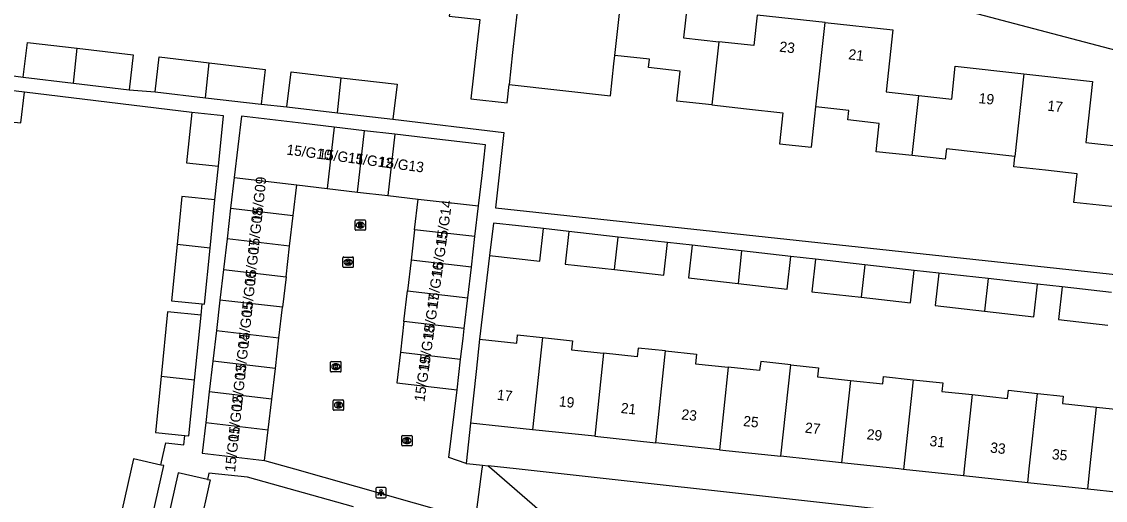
# Model space of a CAD drawing. Extents: x 162026 to 163499, y 387297 to 388169.
# Drawn here: x 162314.8 to 162419.5, y 387747 to 387793.2 of the extents above; entities that cross this region are included whole.
import ezdxf

# ---------------------------------------------------------------- set-up
doc = ezdxf.new("R2010")
doc.units = 0
for name, color, linetype in [('IMGEO_Kolk', 7, 'Continuous'), ('IMGEO_Lichtpunt', 7, 'Continuous'), ('IMGEO_Pand', 7, 'Continuous'), ('IMGEO_Pand_nummerreeks', 7, 'Continuous'), ('IMGEO_Rijbaan_lokaal_open', 7, 'Continuous'), ('IMGEO_Rioolput', 7, 'Continuous'), ('IMGEO_Voetpad_open', 7, 'Continuous')]:
    doc.layers.add(name, color=color, linetype=linetype)

msp = doc.modelspace()

# ---------------------------------------------------------------- linework, layer by layer
at = {"layer": 'IMGEO_Kolk'}
for p, q in [((162345.82, 387769.55), (162345.82, 387770.4)), ((162345.9, 387770.47), (162346.75, 387770.47)), ((162346.31, 387770.25), (162346.33, 387770.25)), ((162346.33, 387769.69), (162346.31, 387769.69)), ((162346.82, 387770.4), (162346.82, 387769.55)), ((162346.75, 387769.47), (162345.9, 387769.47)), ((162344.63, 387759.45), (162344.63, 387760.3)), ((162344.71, 387760.38), (162345.56, 387760.38)), ((162345.63, 387760.3), (162345.63, 387759.45)), ((162345.56, 387759.38), (162344.71, 387759.38)), ((162345.12, 387760.16), (162345.15, 387760.16)), ((162345.14, 387759.6), (162345.12, 387759.6)), ((162351.51, 387752.31), (162351.51, 387753.16)), ((162351.58, 387753.24), (162352.43, 387753.24)), ((162351.99, 387753.01), (162352.02, 387753.01)), ((162352.51, 387753.16), (162352.51, 387752.31)), ((162352.43, 387752.23), (162351.58, 387752.23)), ((162352.02, 387752.46), (162351.99, 387752.46))]:
    msp.add_line(p, q, dxfattribs=at)
for points in [[(162345.82, 387769.55), (162345.82, 387770.4)], [(162345.9, 387770.47), (162346.75, 387770.47)], [(162346.14, 387770.17), (162346.27, 387770.17), (162346.27, 387770.02), (162346.39, 387770.17), (162346.56, 387770.17), (162346.41, 387770.02), (162346.57, 387769.77), (162346.41, 387769.77), (162346.33, 387769.94), (162346.27, 387769.87), (162346.27, 387769.77), (162346.14, 387769.77), (162346.14, 387770.17)], [(162346.82, 387770.4), (162346.82, 387769.55)], [(162346.75, 387769.47), (162345.9, 387769.47)], [(162344.63, 387759.45), (162344.63, 387760.3)], [(162344.71, 387760.38), (162345.56, 387760.38)], [(162345.63, 387760.3), (162345.63, 387759.45)], [(162345.56, 387759.38), (162344.71, 387759.38)], [(162344.95, 387760.08), (162345.08, 387760.08), (162345.08, 387759.92), (162345.21, 387760.08), (162345.37, 387760.08), (162345.23, 387759.93), (162345.38, 387759.68), (162345.23, 387759.68), (162345.14, 387759.84), (162345.08, 387759.77), (162345.08, 387759.68), (162344.95, 387759.68), (162344.95, 387760.08)], [(162351.51, 387752.31), (162351.51, 387753.16)], [(162351.58, 387753.24), (162352.43, 387753.24)], [(162351.83, 387752.93), (162351.95, 387752.93), (162351.95, 387752.78), (162352.08, 387752.93), (162352.24, 387752.93), (162352.1, 387752.78), (162352.25, 387752.53), (162352.1, 387752.53), (162352.01, 387752.7), (162351.95, 387752.63), (162351.95, 387752.53), (162351.83, 387752.53), (162351.83, 387752.93)], [(162352.51, 387753.16), (162352.51, 387752.31)], [(162352.43, 387752.23), (162351.58, 387752.23)]]:
    msp.add_lwpolyline(points, dxfattribs=at)
for centre, start, end in [((162345.9, 387770.4), 91.552, 178.448), ((162345.9, 387770.4), 91.552, 178.448), ((162346.75, 387770.4), 1.552, 88.448), ((162346.75, 387770.4), 1.552, 88.448), ((162345.9, 387769.55), 181.552, 268.448), ((162345.9, 387769.55), 181.552, 268.448), ((162346.75, 387769.55), 271.552, 358.448), ((162346.75, 387769.55), 271.552, 358.448), ((162344.71, 387760.3), 91.552, 178.448), ((162344.71, 387760.3), 91.552, 178.448), ((162345.56, 387760.3), 1.552, 88.448), ((162345.56, 387760.3), 1.552, 88.448), ((162344.71, 387759.45), 181.552, 268.448), ((162344.71, 387759.45), 181.552, 268.448), ((162345.56, 387759.45), 271.552, 358.448), ((162345.56, 387759.45), 271.552, 358.448), ((162351.58, 387753.16), 91.552, 178.448), ((162351.58, 387753.16), 91.552, 178.448), ((162352.43, 387753.16), 1.552, 88.448), ((162352.43, 387753.16), 1.552, 88.448), ((162351.58, 387752.31), 181.552, 268.448), ((162351.58, 387752.31), 181.552, 268.448), ((162352.43, 387752.31), 271.552, 358.448), ((162352.43, 387752.31), 271.552, 358.448)]:
    msp.add_arc(centre, 0.0765, start, end, dxfattribs=at)
for centre, major_axis, ratio, start_param, end_param in [((162346.31, 387769.97), (-0.387, 0.002), 0.722429, 4.712389, 7.853982), ((162346.33, 387769.97), (-0.39, 0.002), 0.717154, 1.570796, 4.712389), ((162345.12, 387759.88), (-0.387, 0.002), 0.722429, 4.712389, 7.853982), ((162345.14, 387759.88), (-0.39, 0.002), 0.717154, 1.570796, 4.712389), ((162351.99, 387752.73), (-0.387, 0.002), 0.722429, 4.712389, 7.853982), ((162352.02, 387752.73), (-0.39, 0.002), 0.717154, 1.570796, 4.712389)]:
    msp.add_ellipse(centre, major_axis=major_axis, ratio=ratio, start_param=start_param, end_param=end_param, dxfattribs=at)
at = {"layer": 'IMGEO_Lichtpunt'}
for p, q in [((162349, 387748.11), (162349, 387747.3)), ((162349, 387748.11), (162349, 387747.3)), ((162349.91, 387748.2), (162349.1, 387748.2)), ((162349.91, 387748.2), (162349.1, 387748.2)), ((162350, 387747.3), (162350, 387748.11)), ((162350, 387747.3), (162350, 387748.11)), ((162349.1, 387747.2), (162349.91, 387747.2)), ((162349.1, 387747.2), (162349.91, 387747.2))]:
    msp.add_line(p, q, dxfattribs=at)
for points in [[(162349.38, 387747.77), (162349.42, 387747.74), (162349.23, 387747.48), (162349.19, 387747.51), (162349.38, 387747.77)], [(162349.48, 387747.72), (162349.53, 387747.72), (162349.53, 387747.4), (162349.48, 387747.4), (162349.48, 387747.72)], [(162349.59, 387747.74), (162349.63, 387747.77), (162349.81, 387747.51), (162349.78, 387747.48), (162349.59, 387747.74)]]:
    msp.add_lwpolyline(points, dxfattribs=at)
msp.add_circle((162349.5, 387747.9), 0.0994, dxfattribs=at)
for centre, start, end in [((162349.1, 387748.11), 90, 180), ((162349.1, 387748.11), 90, 180), ((162349.91, 387748.11), 0, 90), ((162349.91, 387748.11), 0, 90), ((162349.1, 387747.3), 180, 270), ((162349.1, 387747.3), 180, 270), ((162349.91, 387747.3), 270, 0), ((162349.91, 387747.3), 270, 360)]:
    msp.add_arc(centre, 0.0946, start, end, dxfattribs=at)
at = {"layer": 'IMGEO_Pand'}
for points in [[(162372.11, 387789.95), (162373.03, 387798.34)], [(162373.03, 387798.34), (162379.42, 387797.64), (162378.76, 387791.64), (162382.16, 387791.26)], [(162362.89, 387796.24), (162362.22, 387790.21), (162361.89, 387787.14)], [(162352.89, 387795.33), (162356.24, 387794.96), (162356.1, 387793.73), (162359.05, 387793.4), (162358.72, 387790.6), (162358.19, 387785.76), (162361.69, 387785.37), (162361.89, 387787.14)], [(162392.44, 387793.12), (162385.88, 387793.84), (162385.56, 387790.89), (162382.16, 387791.26)], [(162391.54, 387784.98), (162392.44, 387793.12)], [(162392.44, 387793.12), (162399, 387792.4), (162398.35, 387786.42), (162401.51, 387786.07)], [(162314.91, 387787.83), (162315.31, 387791.2), (162320.14, 387790.63)], [(162319.77, 387787.26), (162320.14, 387790.63)], [(162320.14, 387790.63), (162325.55, 387789.99), (162325.15, 387786.62)], [(162382.16, 387791.26), (162381.49, 387785.16)], [(162327.66, 387786.43), (162328.06, 387789.8), (162332.9, 387789.23)], [(162361.89, 387787.14), (162371.68, 387786.05), (162372.02, 387789.13), (162372.11, 387789.95)], [(162381.49, 387785.16), (162378.1, 387785.53), (162378.41, 387788.43), (162375.37, 387788.77), (162375.46, 387789.58), (162372.11, 387789.95)], [(162332.53, 387785.85), (162332.9, 387789.23)], [(162332.9, 387789.23), (162338.31, 387788.59), (162337.91, 387785.22)], [(162401.51, 387786.07), (162404.68, 387785.72), (162405.02, 387788.89), (162411.66, 387788.16)], [(162314.91, 387787.83), (162319.77, 387787.26)], [(162340.41, 387784.99), (162340.81, 387788.36), (162345.65, 387787.79)], [(162345.28, 387784.41), (162345.65, 387787.79)], [(162345.65, 387787.79), (162351.05, 387787.15), (162350.66, 387783.78)], [(162411.66, 387788.16), (162410.78, 387780.19)], [(162411.66, 387788.16), (162418.29, 387787.43), (162417.64, 387781.53), (162420.88, 387781.17)], [(162315.03, 387786.39), (162310.9, 387786.86), (162305.93, 387787.42)], [(162313.29, 387780.17), (162313.67, 387783.54), (162314.69, 387783.42), (162315.03, 387786.39)], [(162319.77, 387787.26), (162325.15, 387786.62)], [(162327.66, 387786.43), (162332.53, 387785.85)], [(162332.53, 387785.85), (162337.91, 387785.22)], [(162400.87, 387780.26), (162401.51, 387786.07)], [(162331.21, 387784.43), (162330.7, 387779.57), (162333.78, 387779.25)], [(162333.78, 387779.25), (162334.28, 387784.11), (162331.21, 387784.43)], [(162340.41, 387784.99), (162345.28, 387784.41)], [(162345.28, 387784.41), (162350.66, 387783.78)], [(162381.49, 387785.16), (162384.83, 387784.79), (162388.36, 387784.4), (162388.03, 387781.41), (162391.11, 387781.07), (162391.44, 387784.06), (162391.54, 387784.98)], [(162400.87, 387780.26), (162397.39, 387780.64), (162397.68, 387783.38), (162394.64, 387783.71), (162394.74, 387784.63), (162391.54, 387784.98)], [(162344.98, 387783.02), (162342.04, 387783.36), (162336, 387784.06), (162335.65, 387781.1), (162335.31, 387778.15)], [(162344.98, 387783.02), (162344.29, 387777.09)], [(162347.91, 387782.67), (162344.98, 387783.02)], [(162347.22, 387776.74), (162347.91, 387782.67)], [(162350.85, 387782.33), (162347.91, 387782.67)], [(162350.85, 387782.33), (162350.16, 387776.4)], [(162358.93, 387775.4), (162359.27, 387778.35), (162359.62, 387781.31), (162353.79, 387781.99), (162350.85, 387782.33)], [(162410.78, 387780.19), (162404.17, 387780.92), (162404.06, 387779.91), (162400.87, 387780.26)], [(162420.17, 387775.34), (162416.5, 387775.75), (162416.81, 387778.51), (162413.74, 387778.85), (162410.67, 387779.18), (162410.78, 387780.19)], [(162335.31, 387778.15), (162334.96, 387775.19)], [(162335.31, 387778.15), (162341.35, 387777.43)], [(162341.01, 387774.48), (162341.35, 387777.43)], [(162341.35, 387777.43), (162344.29, 387777.09)], [(162344.29, 387777.09), (162347.22, 387776.74)], [(162333.44, 387775.98), (162330.25, 387776.3), (162329.79, 387771.69)], [(162332.98, 387771.32), (162333.44, 387775.98)], [(162347.22, 387776.74), (162350.16, 387776.4)], [(162350.16, 387776.4), (162353.1, 387776.06)], [(162352.75, 387773.11), (162353.1, 387776.06)], [(162353.1, 387776.06), (162358.93, 387775.4)], [(162334.96, 387775.19), (162334.62, 387772.23)], [(162334.96, 387775.19), (162341.01, 387774.48)], [(162358.58, 387772.44), (162358.93, 387775.4)], [(162340.66, 387771.53), (162341.01, 387774.48)], [(162352.75, 387773.11), (162352.41, 387770.16)], [(162358.58, 387772.44), (162352.75, 387773.11)], [(162365.2, 387773.21), (162360.39, 387773.75), (162360, 387770.61)], [(162360, 387770.61), (162364.85, 387770.07), (162365.2, 387773.21)], [(162367.66, 387772.93), (162367.31, 387769.79), (162372.08, 387769.26)], [(162372.43, 387772.4), (162367.66, 387772.93)], [(162334.62, 387772.23), (162334.27, 387769.27)], [(162340.66, 387771.53), (162334.62, 387772.23)], [(162358.24, 387769.48), (162358.58, 387772.44)], [(162372.08, 387769.26), (162372.43, 387772.4)], [(162372.08, 387769.26), (162376.86, 387768.72), (162377.21, 387771.86)], [(162377.21, 387771.86), (162372.43, 387772.4)], [(162329.79, 387771.69), (162329.24, 387766.25), (162332.21, 387765.95)], [(162332.98, 387771.32), (162329.79, 387771.69)], [(162332.21, 387765.95), (162332.44, 387765.93), (162332.98, 387771.32)], [(162340.32, 387768.57), (162340.66, 387771.53)], [(162379.59, 387771.6), (162379.24, 387768.45), (162384.02, 387767.92)], [(162384.35, 387771.06), (162379.59, 387771.6)], [(162384.35, 387771.06), (162384.02, 387767.92)], [(162389.12, 387770.53), (162384.35, 387771.06)], [(162352.41, 387770.16), (162352.06, 387767.2)], [(162358.24, 387769.48), (162352.41, 387770.16)], [(162384.02, 387767.92), (162388.76, 387767.38), (162389.12, 387770.53)], [(162391.5, 387770.26), (162391.14, 387767.12), (162395.91, 387766.58)], [(162396.27, 387769.72), (162391.5, 387770.26)], [(162396.27, 387769.72), (162395.91, 387766.58)], [(162401.05, 387769.18), (162396.27, 387769.72)], [(162334.27, 387769.27), (162333.93, 387766.31)], [(162334.27, 387769.27), (162340.32, 387768.57)], [(162357.89, 387766.52), (162358.24, 387769.48)], [(162395.91, 387766.58), (162400.7, 387766.04), (162401.05, 387769.18)], [(162403.43, 387768.92), (162403.08, 387765.78), (162407.85, 387765.24)], [(162408.2, 387768.38), (162403.43, 387768.92)], [(162340.32, 387768.57), (162339.97, 387765.61)], [(162408.2, 387768.38), (162407.85, 387765.24)], [(162407.85, 387765.24), (162412.62, 387764.7), (162412.98, 387767.85)], [(162412.98, 387767.85), (162408.2, 387768.38)], [(162415.36, 387767.58), (162415.01, 387764.44), (162419.77, 387763.9)], [(162420.12, 387767.04), (162415.36, 387767.58)], [(162351.72, 387764.24), (162352.06, 387767.2)], [(162352.06, 387767.2), (162357.89, 387766.52)], [(162357.55, 387763.56), (162357.89, 387766.52)], [(162333.93, 387766.31), (162333.58, 387763.36)], [(162339.97, 387765.61), (162333.93, 387766.31)], [(162339.63, 387762.65), (162339.97, 387765.61)], [(162332.1, 387764.84), (162328.86, 387765.17), (162328.23, 387758.93)], [(162331.47, 387758.56), (162332.1, 387764.84)], [(162333.58, 387763.36), (162333.24, 387760.4)], [(162333.58, 387763.36), (162339.63, 387762.65)], [(162351.72, 387764.24), (162351.38, 387761.28)], [(162357.55, 387763.56), (162351.72, 387764.24)], [(162357.2, 387760.6), (162357.44, 387762.61), (162357.55, 387763.56)], [(162339.29, 387759.69), (162339.63, 387762.65)], [(162359.03, 387762.52), (162358.69, 387759.4), (162358.16, 387754.43)], [(162359.03, 387762.52), (162362.62, 387762.14), (162362.71, 387762.95), (162365.11, 387762.69)], [(162365.11, 387762.69), (162364.15, 387753.79)], [(162365.11, 387762.69), (162368.01, 387762.38), (162367.91, 387761.51), (162371.02, 387761.18)], [(162351.38, 387761.28), (162351.03, 387758.32), (162356.86, 387757.65)], [(162351.38, 387761.28), (162357.2, 387760.6)], [(162377.01, 387761.4), (162374.37, 387761.68), (162374.28, 387760.83), (162371.02, 387761.18)], [(162376.06, 387752.51), (162377.01, 387761.4)], [(162377.01, 387761.4), (162380, 387761.08), (162379.9, 387760.16), (162383.07, 387759.82)], [(162333.24, 387760.4), (162332.89, 387757.44)], [(162339.29, 387759.69), (162333.24, 387760.4)], [(162356.86, 387757.65), (162357.2, 387760.6)], [(162371.02, 387761.18), (162370.16, 387753.15)], [(162389.12, 387760.06), (162386.21, 387760.37), (162386.11, 387759.5), (162383.07, 387759.82)], [(162338.94, 387756.74), (162339.29, 387759.69)], [(162383.07, 387759.82), (162382.22, 387751.85)], [(162388.17, 387751.22), (162389.12, 387760.06)], [(162389.12, 387760.06), (162391.79, 387759.77), (162391.7, 387758.89), (162394.88, 387758.55)], [(162328.23, 387758.93), (162327.69, 387753.52), (162330.55, 387753.24)], [(162331.47, 387758.56), (162328.23, 387758.93)], [(162330.55, 387753.24), (162330.93, 387753.2), (162331.47, 387758.56)], [(162394.88, 387758.55), (162394.02, 387750.59)], [(162394.88, 387758.55), (162398.01, 387758.21), (162398.09, 387758.92), (162400.96, 387758.61)], [(162400.96, 387758.61), (162400.03, 387749.95)], [(162400.96, 387758.61), (162403.83, 387758.31), (162403.74, 387757.49), (162406.67, 387757.18)], [(162332.89, 387757.44), (162332.55, 387754.48)], [(162338.94, 387756.74), (162332.89, 387757.44)], [(162406.67, 387757.18), (162405.9, 387750), (162405.83, 387749.33)], [(162406.67, 387757.18), (162410.08, 387756.81), (162410.16, 387757.6), (162412.96, 387757.3)], [(162412.04, 387748.66), (162412.18, 387750), (162412.96, 387757.3)], [(162412.96, 387757.3), (162415.47, 387757.04), (162415.39, 387756.31), (162418.69, 387755.96)], [(162338.6, 387753.78), (162338.94, 387756.74)], [(162418.69, 387755.96), (162421.71, 387755.63), (162421.8, 387756.46), (162424.78, 387756.14)], [(162417.84, 387748.04), (162418.05, 387750), (162418.69, 387755.96)], [(162332.55, 387754.48), (162332.21, 387751.52), (162333.29, 387751.4), (162338.25, 387750.82)], [(162332.55, 387754.48), (162338.6, 387753.78)], [(162364.15, 387753.79), (162358.16, 387754.43)], [(162338.25, 387750.82), (162338.6, 387753.78)], [(162370.16, 387753.15), (162364.15, 387753.79)], [(162370.16, 387753.15), (162376.06, 387752.51)], [(162382.22, 387751.85), (162376.06, 387752.51)], [(162382.22, 387751.85), (162388.17, 387751.22)], [(162328.21, 387750.38), (162325.57, 387750.98), (162324.48, 387746.13)], [(162394.02, 387750.59), (162388.17, 387751.22)], [(162327.41, 387745.47), (162328.5, 387750.32), (162328.21, 387750.38)], [(162400.03, 387749.95), (162399.56, 387750), (162394.02, 387750.59)], [(162405.83, 387749.33), (162400.03, 387749.95)], [(162332.74, 387748.99), (162329.89, 387749.63), (162328.83, 387744.88)], [(162332.74, 387748.99), (162332.97, 387748.94), (162331.91, 387744.19), (162328.83, 387744.88)], [(162412.04, 387748.66), (162405.83, 387749.33)], [(162417.84, 387748.04), (162412.04, 387748.66)], [(162423.85, 387747.4), (162417.84, 387748.04)]]:
    msp.add_lwpolyline(points, dxfattribs=at)
at = {"layer": 'IMGEO_Rijbaan_lokaal_open'}
for points in [[(162357.75, 387750.54), (162356.07, 387751.11), (162356.86, 387757.65)], [(162338.25, 387750.82), (162341.15, 387750), (162358.62, 387745.05)], [(162357.75, 387750.54), (162357.8, 387750.52), (162359.31, 387750.36)], [(162359.31, 387750.36), (162359.26, 387750), (162358.62, 387745.05)]]:
    msp.add_lwpolyline(points, dxfattribs=at)
at = {"layer": 'IMGEO_Rioolput'}
for p, q in [((162347, 387773.13), (162347, 387773.98)), ((162347.08, 387774.05), (162347.93, 387774.05)), ((162347.49, 387773.83), (162347.52, 387773.83)), ((162348, 387773.98), (162348, 387773.13)), ((162347.93, 387773.05), (162347.08, 387773.05)), ((162347.51, 387773.27), (162347.49, 387773.27)), ((162344.89, 387755.74), (162344.89, 387756.59)), ((162344.96, 387756.67), (162345.82, 387756.67)), ((162345.38, 387756.45), (162345.4, 387756.45)), ((162345.89, 387756.59), (162345.89, 387755.74)), ((162345.82, 387755.67), (162344.96, 387755.67)), ((162345.4, 387755.89), (162345.37, 387755.89))]:
    msp.add_line(p, q, dxfattribs=at)
for points in [[(162347, 387773.13), (162347, 387773.98)], [(162347.08, 387774.05), (162347.93, 387774.05)], [(162348, 387773.98), (162348, 387773.13)], [(162347.93, 387773.05), (162347.08, 387773.05)], [(162347.59, 387773.75), (162347.34, 387773.75), (162347.34, 387773.35)], [(162347.34, 387773.35), (162347.46, 387773.35), (162347.46, 387773.51), (162347.47, 387773.51)], [(162347.52, 387773.67), (162347.46, 387773.67), (162347.46, 387773.59)], [(162347.46, 387773.59), (162347.51, 387773.59)], [(162347.52, 387773.48), (162347.59, 387773.35), (162347.73, 387773.35), (162347.67, 387773.48)], [(162344.89, 387755.74), (162344.89, 387756.59)], [(162344.96, 387756.67), (162345.82, 387756.67)], [(162345.48, 387756.37), (162345.22, 387756.37), (162345.22, 387755.97)], [(162345.22, 387755.97), (162345.35, 387755.97), (162345.35, 387756.13), (162345.36, 387756.13)], [(162345.4, 387756.29), (162345.35, 387756.29), (162345.35, 387756.21)], [(162345.35, 387756.21), (162345.4, 387756.21)], [(162345.41, 387756.1), (162345.48, 387755.97), (162345.62, 387755.97), (162345.55, 387756.09)], [(162345.89, 387756.59), (162345.89, 387755.74)], [(162345.82, 387755.67), (162344.96, 387755.67)]]:
    msp.add_lwpolyline(points, dxfattribs=at)
for centre, radius, start, end in [((162347.08, 387773.98), 0.0765, 91.552, 178.448), ((162347.08, 387773.98), 0.0765, 91.552, 178.448), ((162347.93, 387773.98), 0.0765, 1.552, 88.448), ((162347.93, 387773.98), 0.0765, 1.552, 88.448), ((162347.08, 387773.13), 0.0765, 181.552, 268.448), ((162347.08, 387773.13), 0.0765, 181.552, 268.448), ((162347.47, 387773.46), 0.0533, 26.0293, 88.6989), ((162347.5, 387773.78), 0.19, 274.7715, 282.9687), ((162347.52, 387773.57), 0.0964, 77.0061, 93.1865), ((162347.54, 387773.63), 0.0378, 276.6634, 79.6772), ((162347.59, 387773.64), 0.109, 350.3612, 89.416), ((162347.59, 387773.64), 0.112, 277.5842, 350.9817), ((162347.57, 387773.42), 0.108, 29.5134, 73.7905), ((162347.93, 387773.13), 0.0765, 271.552, 358.448), ((162347.93, 387773.13), 0.0765, 271.552, 358.448), ((162344.96, 387756.59), 0.0765, 91.552, 178.448), ((162344.96, 387756.59), 0.0765, 91.552, 178.448), ((162345.36, 387756.08), 0.0533, 26.0293, 88.6989), ((162345.41, 387756.19), 0.0964, 77.0061, 93.1865), ((162345.39, 387756.4), 0.19, 274.7715, 282.9687), ((162345.42, 387756.25), 0.0378, 276.6634, 79.6772), ((162345.48, 387756.26), 0.109, 350.3612, 89.416), ((162345.47, 387756.26), 0.112, 277.5842, 350.9817), ((162345.46, 387756.04), 0.108, 29.5134, 73.7905), ((162345.81, 387756.59), 0.0765, 1.552, 88.448), ((162345.81, 387756.59), 0.0765, 1.552, 88.448), ((162344.96, 387755.74), 0.0765, 181.552, 268.448), ((162344.96, 387755.74), 0.0765, 181.552, 268.448), ((162345.81, 387755.74), 0.0765, 271.552, 358.448), ((162345.81, 387755.74), 0.0765, 271.552, 358.448)]:
    msp.add_arc(centre, radius, start, end, dxfattribs=at)
for centre, major_axis, ratio, start_param, end_param in [((162347.49, 387773.55), (-0.387, 0.002), 0.722429, 4.712389, 7.853982), ((162347.51, 387773.55), (-0.39, 0.002), 0.717154, 1.570796, 4.712389), ((162345.38, 387756.17), (-0.387, 0.002), 0.722429, 4.712389, 7.853982), ((162345.4, 387756.17), (-0.39, 0.002), 0.717154, 1.570796, 4.712389)]:
    msp.add_ellipse(centre, major_axis=major_axis, ratio=ratio, start_param=start_param, end_param=end_param, dxfattribs=at)
at = {"layer": 'IMGEO_Voetpad_open'}
for points in [[(162302.74, 387811.36), (162304.73, 387812.66), (162306.96, 387812.39), (162360.93, 387806.15), (162438.18, 387785.81), (162484.71, 387780.32)], [(162313.5, 387788.05), (162314.91, 387787.83)], [(162331.21, 387784.43), (162315.03, 387786.39)], [(162325.15, 387786.62), (162327.66, 387786.43)], [(162337.91, 387785.22), (162340.41, 387784.99)], [(162350.66, 387783.78), (162361.38, 387782.51), (162360.57, 387775.22), (162425, 387768.3), (162427.31, 387767.66), (162435.36, 387763.78), (162433.89, 387752.27), (162448.74, 387751.33)], [(162333.44, 387775.98), (162333.78, 387779.25)], [(162367.66, 387772.93), (162365.2, 387773.21)], [(162379.59, 387771.6), (162377.21, 387771.86)], [(162360, 387770.61), (162359.03, 387762.52)], [(162391.5, 387770.26), (162389.12, 387770.53)], [(162403.43, 387768.92), (162401.05, 387769.18)], [(162415.36, 387767.58), (162412.98, 387767.85)], [(162332.1, 387764.84), (162332.21, 387765.95)], [(162358.16, 387754.43), (162357.75, 387750.54)], [(162328.21, 387750.38), (162328.28, 387750.68), (162328.7, 387752.52), (162330.44, 387752.32), (162330.55, 387753.24)], [(162359.31, 387750.36), (162359.87, 387750.3)], [(162431.24, 387742.32), (162427.03, 387742.86), (162362.56, 387750), (162359.87, 387750.3)], [(162359.87, 387750.3), (162360.21, 387750), (162366.56, 387744.51)], [(162346.84, 387746.35), (162336.59, 387749.19), (162332.87, 387749.58), (162332.74, 387748.99)]]:
    msp.add_lwpolyline(points, dxfattribs=at)

# ---------------------------------------------------------------- texts
at = {"layer": 'IMGEO_Pand_nummerreeks'}
for s, rotation, p in [('23', 353.7261, (162387.98, 387790.31)), ('21', 353.724, (162394.65, 387789.57)), ('19', 353.721, (162407.25, 387785.34)), ('17', 353.7204, (162413.89, 387784.61)), ('15/G10', 352.5041, (162340.32, 387780.37)), ('15/G11', 352.5041, (162343.4, 387779.97)), ('15/G12', 352.5041, (162346.25, 387779.59)), ('15/G13', 352.5041, (162349.23, 387779.2)), ('15/G09', 83.9193, (162337.96, 387773.81)), ('15/G08', 83.9193, (162337.63, 387770.79)), ('15/G14', 82.1467, (162355.79, 387771.55)), ('15/G15', 82.1467, (162355.37, 387768.53)), ('15/G07', 83.9193, (162337.31, 387767.75)), ('15/G16', 82.1467, (162354.95, 387765.51)), ('15/G06', 83.9193, (162336.99, 387764.72)), ('15/G17', 82.1467, (162354.54, 387762.49)), ('15/G05', 83.9193, (162336.67, 387761.69)), ('15/G18', 82.1467, (162354.12, 387759.47)), ('15/G04', 83.9193, (162336.34, 387758.66)), ('15/G19', 82.1467, (162353.7, 387756.44)), ('15/G03', 83.9193, (162336.02, 387755.63)), ('17', 353.8932, (162360.68, 387756.69)), ('15/G02', 83.9193, (162335.7, 387752.59)), ('19', 353.8932, (162366.66, 387756.05)), ('21', 353.8932, (162372.65, 387755.41)), ('23', 353.8932, (162378.51, 387754.79)), ('25', 353.8932, (162384.48, 387754.15)), ('15/G01', 83.9193, (162335.39, 387749.67)), ('27', 353.8932, (162390.45, 387753.51)), ('29', 353.8932, (162396.42, 387752.87)), ('31', 353.8932, (162402.5, 387752.22)), ('33', 353.8932, (162408.36, 387751.59)), ('35', 353.8932, (162414.33, 387750.95))]:
    msp.add_text(s, height=1, rotation=rotation, dxfattribs=at).set_placement(p)

doc.saveas('drawing.dxf')
